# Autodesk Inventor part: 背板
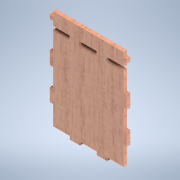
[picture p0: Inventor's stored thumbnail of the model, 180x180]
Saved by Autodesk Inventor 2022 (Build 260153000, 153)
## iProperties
Created: 2024-11
Part Number: 背板
Material: 木 (オーク)
Document SubType Name: Modeling
Designer: shimizu
Density: 0.76 g/cm^3
Appearance: ホワイト オーク材 - ナチュラル 標準の光沢
Author: shimizu
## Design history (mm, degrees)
sketch "スケッチ1"
  geometry: L1 (-32.841, 27.318)-(22.159, 27.318); L2 (-11.841, 17.318)-(-11.841, 14.818); L3 (-11.841, 14.818)-(-19.841, 14.818); L4 (-19.841, 14.818)-(-19.841, 17.318); L5 (9.159, 17.318)-(9.159, 14.818); L6 (9.159, 14.818)-(1.159, 14.818); L7 (1.159, 14.818)-(1.159, 17.318); L8 (-32.841, 23.818)-(-35.341, 23.818); L9 (-35.341, 23.818)-(-35.341, 20.818); L10 (-35.341, 20.818)-(-32.841, 20.818); L11 (22.159, 23.818)-(24.659, 23.818); L12 (24.659, 23.818)-(24.659, 20.818); L13 (24.659, 20.818)-(22.159, 20.818); L14 (-32.841, 17.318)-(-32.841, 20.818); L15 (-32.841, 23.818)-(-32.841, 27.318); L16 (22.159, 27.318)-(22.159, 23.818); L17 (22.159, 20.818)-(22.159, 17.318); L18 (22.159, 17.318)-(9.159, 17.318); L19 (1.159, 17.318)-(-11.841, 17.318); L20 (-19.841, 17.318)-(-32.841, 17.318); L21 (-32.841, 14.818)-(22.159, 14.818); L22 (22.159, 14.818)-(22.159, -50.182); L23 (22.159, -50.182)-(-32.841, -50.182); L24 (-32.841, -50.182)-(-32.841, 14.818); L25 (22.159, -0.182)-(24.659, -0.182); L26 (24.659, -0.182)-(24.659, -10.182); L27 (24.659, -10.182)-(22.159, -10.182); L28 (22.159, -10.182)-(22.159, -0.182); L29 (22.159, -25.182)-(24.659, -25.182); L30 (24.659, -25.182)-(24.659, -35.182); L31 (24.659, -35.182)-(22.159, -35.182); L32 (22.159, -35.182)-(22.159, -25.182); L33 (-32.841, -0.182)-(-35.341, -0.182); L34 (-35.341, -0.182)-(-35.341, -10.182); L35 (-35.341, -10.182)-(-32.841, -10.182); L36 (-32.841, -10.182)-(-32.841, -0.182); L37 (-32.841, -25.182)-(-35.341, -25.182); L38 (-35.341, -25.182)-(-35.341, -35.182); L39 (-35.341, -35.182)-(-32.841, -35.182); L40 (-32.841, -35.182)-(-32.841, -25.182); L41 (-19.841, -50.182)-(-11.841, -50.182); L42 (-11.841, -50.182)-(-11.841, -52.682); L43 (-11.841, -52.682)-(-19.841, -52.682); L44 (-19.841, -52.682)-(-19.841, -50.182); L45 (1.159, -50.182)-(9.159, -50.182); L46 (9.159, -50.182)-(9.159, -52.682); L47 (9.159, -52.682)-(1.159, -52.682); L48 (1.159, -52.682)-(1.159, -50.182); 11 further points
  constraints: 96 end point, 25 parallel, 11 perpendicular, 10 horizontal, 7 point on line
  dimensions: "d16" = 13 distance of L17.end L5.start; "d17" = 13 distance of L4.end L14.start; "d18" = 8 distance of L5.end L6.end; "d19" = 8 distance of L2.end L3.end; "d20" = 13 distance of L7.end L2.start; "d21" = 55 distance between parallel lines of L16 L15; "d22" = 60 distance between parallel lines of L12 L9; "d23" = 65 distance between parallel lines of L23 L21; "d24" = 55 distance between parallel lines of L22 L24; "d25" = 10 distance between parallel lines of L27 L25; "d26" = 10 distance between parallel lines of L31 L29; "d27" = 10 distance between parallel lines of L35 L33; "d28" = 10 distance between parallel lines of L39 L37; "d29" = 15 distance between parallel lines of L31 L23; "d30" = 15 distance between parallel lines of L27 L29; "d31" = 15 distance between parallel lines of L39 L23; "d32" = 15 distance between parallel lines of L35 L37; "d33" = 2.5 distance between parallel lines of L22 L26; "d34" = 2.5 distance between parallel lines of L32 L30; "d35" = 2.5 distance between parallel lines of L36 L34; "d36" = 2.5 distance between parallel lines of L38 L24; "d37" = 2.5 distance of L43.end L41.start; "d38" = 2.5 distance of L45.end L46.end
extrude "押し出し1" new body sketch "スケッチ1" distance "d14" = 2.5; taper "d15" = 0 deg
node "ソリッド1"
